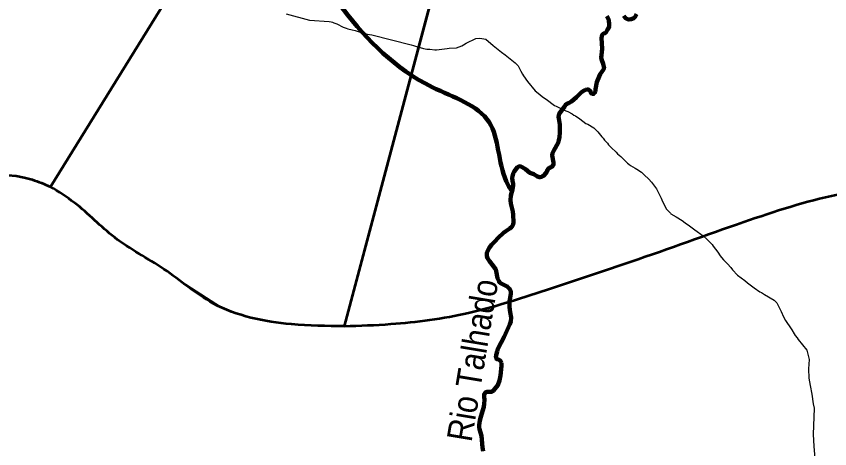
# Model space of a CAD drawing. Extents: x -1643653 to 4543381, y 1624270 to 13878484.
# Drawn here: x 611751 to 627893, y 8951494 to 8960077 of the extents above; entities that cross this region are included whole.
import ezdxf
from ezdxf.enums import TextEntityAlignment as Align

# ---------------------------------------------------------------- set-up
doc = ezdxf.new("R2010")
doc.units = 0
doc.header["$LTSCALE"] = 200
for name, color, linetype, lineweight in [('12', 7, 'Continuous', 25), ('23', 7, 'Continuous', 13), ('24', 7, 'Continuous', 25), ('28', 7, 'Continuous', 53), ('60', 7, 'Continuous', 13), ('9', 7, 'Continuous', 90)]:
    doc.layers.add(name, color=color, linetype=linetype, lineweight=lineweight)
doc.layers.add('49', color=7, linetype='Continuous')

msp = doc.modelspace()

# ---------------------------------------------------------------- linework, layer by layer
at = {"layer": '12'}
for points in [[(617107.9, 8960123.1), (617571.3, 8960000.1), (617961.2, 8959971.1), (617997, 8959967.1), (618026, 8959959.2), (618054, 8959949.2), (618114.7, 8959924.2), (618235.7, 8959862.3), (618293.7, 8959838.4), (618327.5, 8959827.4), (618413, 8959804.5), (618473.5, 8959791.6), (618533.2, 8959772.7), (618617.9, 8959748.8), (618652.5, 8959740.8), (618682.4, 8959731.8), (618711.4, 8959723.9), (618803.6, 8959709), (619586.3, 8959511.3)], [(619831.3, 8959436.2), (619865.1, 8959428.2), (619897.1, 8959423.3), (619929, 8959423.3), (619960.1, 8959421.4), (620056, 8959410.5), (620088, 8959410.6), (620193.3, 8959426.8), (620302, 8959438.9), (620338.3, 8959444), (620485.1, 8959452.2), (620592.3, 8959491.5), (620626.6, 8959508.6), (620677.1, 8959543.7), (620866.8, 8959636.1), (620950.1, 8959645.3), (621067.6, 8959622.4), (621213.8, 8959498.5), (621277.5, 8959446.5), (621310.7, 8959416.5), (621378.9, 8959364.5), (621451.2, 8959312.6), (621517.4, 8959257.6), (621620.6, 8959177.6), (621652, 8959151.6), (621681.1, 8959122.6), (621709.4, 8959090.6), (621730.8, 8959055.6), (621766, 8958989.6), (621797.6, 8958926.5), (621816.7, 8958894.5), (621897.9, 8958779.4), (622047.1, 8958598.4), (622104.4, 8958547.4), (622189, 8958482.4), (622295.2, 8958408.5), (622402.8, 8958323.5), (622432, 8958306.5), (622464.2, 8958290.6), (622503.3, 8958272.6), (622656.9, 8958198.7), (622695.9, 8958184.8), (622781.7, 8958137.8), (622814.5, 8958116.8), (622845, 8958100.9), (622933, 8958040.9), (622994, 8957997), (623055.6, 8957949), (623090.1, 8957935), (623208.6, 8957861.1), (623261.3, 8957811.1), (623293.1, 8957783.1), (623319, 8957753.1), (623370.1, 8957684.1), (623394.1, 8957657.1), (623423, 8957618), (623480.8, 8957556), (623503.5, 8957528), (623577.3, 8957455), (623634.3, 8957397), (623656.2, 8957377), (623681.5, 8957349), (623715.2, 8957318), (623746.4, 8957294), (623796.4, 8957250.1), (623820, 8957220), (623881.1, 8957162.1), (623907.7, 8957139.1), (623938.3, 8957116.1), (624032.6, 8957060.1), (624097.3, 8957025.2), (624126.4, 8957005.2), (624156.6, 8956982.2), (624209.6, 8956933.2), (624300.1, 8956843.2), (624356.6, 8956783.2), (624452.3, 8956653.2), (624547.5, 8956464), (624563.3, 8956437), (624643.8, 8956253.8), (624732.1, 8956169.8), (624741.4, 8956157.8), (624844.8, 8956096.9), (624963, 8956021), (625024.6, 8955976), (625106.9, 8955919.1), (625134.8, 8955896.1), (625215.8, 8955838.1), (625381.6, 8955722.2), (625453.3, 8955650.2), (625539.4, 8955570.2), (625559, 8955549.2), (625578.1, 8955517.2), (625672.3, 8955394.1), (625719.6, 8955321.1), (625744.1, 8955288.1), (625787.2, 8955246.1), (625865, 8955162.1), (625928.3, 8955090.1), (625962.8, 8955044), (626062.5, 8954941)], [(619586.3, 8959511.3), (619636.3, 8959496), (619674.1, 8959485), (619831.3, 8959436.2)], [(626062.5, 8954941), (626210.1, 8954830.1), (626263.6, 8954786.1), (626369.3, 8954710.2), (626395.7, 8954688.2), (626508.6, 8954610.2), (626539.2, 8954592.2), (626598.2, 8954554.3), (626792.1, 8954439.4), (626840.8, 8954390.4), (626864.8, 8954350.4), (626929.5, 8954214.3), (626976, 8954113.2), (627012.7, 8954042.1), (627056.3, 8953977.1), (627085.1, 8953931.1), (627140.4, 8953852), (627187.4, 8953773), (627209.8, 8953740), (627243.8, 8953694), (627268.1, 8953665), (627437.5, 8953449.9)], [(627437.5, 8953449.9), (627481.8, 8953267.7), (627474.2, 8953079.4), (627481, 8952894.1), (627502, 8952745.9), (627539.5, 8952577.7), (627565.1, 8952382.4), (627583.5, 8952301.3), (627578.9, 8952122), (627564.2, 8951783.5), (627578, 8951538.1), (627594.5, 8951309.8), (627615.6, 8951152.6), (627641.3, 8950944.3), (627690, 8950694), (627726.6, 8950540.8), (627780.8, 8950380.6), (627876.2, 8950172.5), (627886.3, 8950067.3), (627860.6, 8949911), (627825.7, 8949779.8), (627813.3, 8949686.6)]]:
    msp.add_lwpolyline(points, dxfattribs=at)
at = {"layer": '23'}
msp.add_lwpolyline([(612430.2, 8956693.8), (612747.6, 8956491.3), (613132.8, 8956184), (613551.6, 8955800.6), (614057.6, 8955452.3), (614550.7, 8955141.9), (615023.2, 8954818.1), (615915.6, 8954244.4), (616589.2, 8954040), (617511.2, 8953947.5), (618207.3, 8953925.8), (618257.6, 8953925.9)], dxfattribs=at)
msp.add_lwpolyline([(612430.2, 8956693.8), (612747.6, 8956491.3), (613132.8, 8956184), (613551.6, 8955800.6), (614057.6, 8955452.3), (614550.7, 8955141.9), (615023.2, 8954818.1), (615915.6, 8954244.4), (616589.2, 8954040), (617511.2, 8953947.5), (618207.3, 8953925.8), (618257.6, 8953925.9)], dxfattribs=at)
for points in [[(606946.8, 8954087), (607164, 8954388.6), (607396.1, 8954883.6), (607870.9, 8955517.4), (608625.2, 8956035.7), (609416.9, 8956401.3), (612068.3, 8956835.4), (612430.2, 8956693.8)], [(606946.8, 8954087), (607164, 8954388.6), (607396.1, 8954883.6), (607870.9, 8955517.4), (608625.2, 8956035.7), (609416.9, 8956401.3), (612068.3, 8956835.4), (612430.2, 8956693.8)], [(618257.6, 8953925.9), (619183.7, 8953970.3), (620725.9, 8954192.9), (622371.6, 8954682.1), (623953.8, 8955209.7), (626185.5, 8955995.2), (628043.5, 8956541.4), (631351.2, 8956802.4), (633709.5, 8956728.8), (635993.8, 8956280.5), (637686.3, 8955648.2), (639291.4, 8954828.8), (640588.9, 8953973.3), (641709, 8952948.6), (643376.9, 8951340.4), (644721.9, 8950215.5), (645793.1, 8949290.9)], [(618257.6, 8953925.9), (619183.7, 8953970.3), (620725.9, 8954192.9), (622371.6, 8954682.1), (623953.8, 8955209.7), (626185.5, 8955995.2), (628043.5, 8956541.4), (631351.2, 8956802.4), (633709.5, 8956728.8), (635993.8, 8956280.5), (637686.3, 8955648.2), (639291.4, 8954828.8), (640588.9, 8953973.3), (641709, 8952948.6), (643376.9, 8951340.4), (644721.9, 8950215.5), (645793.1, 8949290.9)]]:
    msp.add_spline(points, degree=3, dxfattribs=at)
at = {"layer": '24'}
for points in [[(624056.4, 8960117.9), (624029.7, 8960062.8), (624008.5, 8960040.7), (623952.6, 8960017.6), (623906.6, 8960011.5), (623879.7, 8960018.5), (623839.9, 8960041.5), (623809.1, 8960087.5)], [(623469.3, 8960080), (623503, 8960016.9), (623511.8, 8959991.9), (623518.8, 8959918.8), (623515.2, 8959871.7), (623503, 8959841.6), (623483.8, 8959814.6), (623458.3, 8959764.4), (623435.3, 8959743.4), (623405.8, 8959733.3), (623380.1, 8959708.2), (623370, 8959684.2), (623363, 8959639.1), (623374, 8959437.8), (623371.3, 8959365.7), (623362.7, 8959309.6), (623359.5, 8959254.5), (623367, 8959203.4), (623399.7, 8959131.4), (623414.8, 8959045.2), (623404.2, 8959022.2), (623338.3, 8958926.9), (623315, 8958880.8), (623272.9, 8958769.6), (623243.1, 8958633.3), (623241.6, 8958590.3), (623234, 8958561.2), (623207.1, 8958537.1), (623180.9, 8958538.1), (623154, 8958559.1), (623142.4, 8958588.1), (623129.2, 8958606.1), (623114.3, 8958616.1), (623091.3, 8958624.1), (623048.1, 8958618)], [(623048.1, 8958618), (623008.6, 8958598.9), (622961, 8958563.8), (622867, 8958474.5), (622765.3, 8958385.2), (622710.3, 8958350.1), (622672.6, 8958336), (622645.8, 8958310.9), (622635.8, 8958292.8), (622526.4, 8958139.4), (622516.5, 8958114.4), (622511.7, 8958078.3), (622515.3, 8958048.3), (622533.3, 8957971.2), (622537.7, 8957930.1), (622539.2, 8957771.9), (622532.6, 8957678.7), (622519.6, 8957617.6), (622503, 8957566.5), (622414.7, 8957413.1), (622392.8, 8957358), (622387.2, 8957313.9), (622413.1, 8957173.7), (622412, 8957144.7), (622401.3, 8957121.6), (622379.3, 8957091.6), (622329.5, 8957067.4), (622303.6, 8957046.4), (622292.3, 8957028.3), (622277.2, 8956988.2), (622224.7, 8956922.1), (622199.4, 8956902), (622173.6, 8956888.9), (622144.5, 8956882.9), (622124.1, 8956884.8), (622082.2, 8956903.8), (622023.4, 8956940.8)], [(622023.4, 8956940.8), (621940, 8956970.7), (621852.9, 8957044.7), (621852.9, 8957044.7), (621788.3, 8957084.6), (621747.1, 8957098.6), (621722, 8957094.5), (621699.9, 8957079.5), (621630.5, 8956993.2), (621609.1, 8956955.1), (621593, 8956869), (621597.7, 8956809.9), (621609.5, 8956752.8), (621610.3, 8956716.8), (621596.7, 8956635.6), (621564.2, 8956517.4), (621555.7, 8956425.2), (621563.4, 8956363.1), (621602.1, 8956205), (621612.3, 8956132.8), (621617.2, 8955989.6), (621609.4, 8955942.6), (621581.9, 8955900.4), (621546.5, 8955864.3), (621462.3, 8955810.1), (621421.6, 8955778), (621315.5, 8955681.7), (621248.5, 8955606.5), (621180.3, 8955539.2), (621144.2, 8955490.1), (621090.8, 8955387.9), (621089.6, 8955318.8), (621102.6, 8955276.7), (621141.2, 8955216.7), (621216.2, 8955123.7), (621263.9, 8955050.6), (621273.7, 8955018.6), (621298.4, 8954880.4), (621326.6, 8954818.3), (621344.8, 8954792.3), (621361.2, 8954778.3), (621494.9, 8954716.5), (621540.7, 8954668.5), (621556.5, 8954637.4), (621563.9, 8954607.4), (621564.5, 8954574.3), (621548.8, 8954491.2), (621540.9, 8954424.1), (621539.7, 8954301.9), (621548, 8954202.7), (621568.6, 8954096.6), (621562.7, 8954019.5), (621547, 8953964.4), (621433.8, 8953717.8), (621371.7, 8953602.5), (621309.6, 8953474.2), (621290.3, 8953424.1), (621271.3, 8953352), (621268.5, 8953307.9), (621278.3, 8953276.9), (621286.8, 8953268.9), (621318.5, 8953261.9), (621350.1, 8953247.9), (621369.2, 8953222.9), (621379.6, 8953197.9)], [(621379.6, 8953197.9), (621378.8, 8953137.8), (621359.7, 8952949.5), (621342.4, 8952846.3), (621307.8, 8952755.1), (621249.5, 8952681.9), (621219.1, 8952650.8), (621195, 8952631.7), (621171.1, 8952622.7), (621146.2, 8952620.6), (621100.1, 8952625.6), (621079.8, 8952621.5), (621057, 8952606.5), (621039.6, 8952581.4), (621035.3, 8952565.4), (621033.6, 8952527.3), (621045.1, 8952461.2), (621037.1, 8952383.1), (621025.7, 8952328), (620968.5, 8952127.6), (620952.3, 8952055.4), (620937.5, 8951961.3), (620936.1, 8951922.2), (620941.1, 8951883.2), (620980.3, 8951750), (621003, 8951516.7), (621017.4, 8951444.6)]]:
    msp.add_lwpolyline(points, dxfattribs=at)
at = {"layer": '28'}
msp.add_line((621434.1, 8965861.3), (618257.6, 8953925.9), dxfattribs=at)
for points in [[(620631.9, 8965673.6), (621434.1, 8965861.3), (618257.6, 8953925.9), (618257.6, 8953925.9)], [(612430.1, 8956693.8), (617911.2, 8965554.7), (618251.3, 8965287.2), (618322.3, 8965231.4)], [(612430.2, 8956693.8), (617911.2, 8965554.7), (618251.3, 8965287.2), (618322.3, 8965231.4)]]:
    msp.add_lwpolyline(points, dxfattribs=at)
for points in [[(606956.6, 8954077.8), (607164, 8954388.6), (607396.1, 8954883.6), (607870.9, 8955517.4), (608625.2, 8956035.7), (609416.9, 8956401.3), (612068.3, 8956835.4), (612430.2, 8956693.8)], [(618257.6, 8953925.9), (619183.7, 8953970.3), (620725.9, 8954192.9), (622371.6, 8954682.1), (623953.8, 8955209.7), (626185.5, 8955995.2), (628043.5, 8956541.4), (631351.2, 8956802.4), (633709.5, 8956728.8), (635993.8, 8956280.5), (637686.3, 8955648.2), (639291.4, 8954828.8), (640588.9, 8953973.3), (641709, 8952948.6), (643376.9, 8951340.4), (644721.9, 8950215.5), (645793.1, 8949290.9)], [(618257.6, 8953925.9), (617209.7, 8953965.7), (615658.4, 8954379), (614681.6, 8955057.1), (613704.6, 8955684.2), (612906.2, 8956374.2), (612430.2, 8956693.8)]]:
    msp.add_spline(points, degree=3, dxfattribs=at)
at = {"layer": '60', "lineweight": 25}
msp.add_spline([(814781, 9009175.5), (814787.2, 9009173.4), (814796.9, 9009173.4), (814799.4, 9009172.4), (814805.1, 9009174.5), (814805.6, 9009176.5), (814811.7, 9009179.5), (814811.7, 9009179.5), (814801.5, 9009181), (814790.7, 9009181.5), (814784.1, 9009183.1), (814777.4, 9009185.1), (814778.4, 9009175.5)], degree=3, dxfattribs=at)
at = {"layer": '9'}
for points in [[(624056.4, 8960117.9), (624029.7, 8960062.8), (624008.5, 8960040.7), (623952.6, 8960017.6), (623906.6, 8960011.5), (623879.7, 8960018.5), (623839.9, 8960041.5), (623809.1, 8960087.5)], [(623469.3, 8960080), (623503, 8960016.9), (623511.8, 8959991.9), (623518.8, 8959918.8), (623515.2, 8959871.7), (623503, 8959841.6), (623483.8, 8959814.6), (623458.3, 8959764.4), (623435.3, 8959743.4), (623405.8, 8959733.3), (623380.1, 8959708.2), (623370, 8959684.2), (623363, 8959639.1), (623374, 8959437.8), (623371.3, 8959365.7), (623362.7, 8959309.6), (623359.5, 8959254.5), (623367, 8959203.4), (623399.7, 8959131.4), (623414.8, 8959045.2), (623404.2, 8959022.2), (623338.3, 8958926.9), (623315, 8958880.8), (623272.9, 8958769.6), (623243.1, 8958633.3), (623241.6, 8958590.3), (623234, 8958561.2), (623207.1, 8958537.1), (623180.9, 8958538.1), (623154, 8958559.1), (623142.4, 8958588.1), (623129.2, 8958606.1), (623114.3, 8958616.1), (623091.3, 8958624.1), (623048.1, 8958618)], [(623048.1, 8958618), (623008.6, 8958598.9), (622961, 8958563.8), (622867, 8958474.5), (622765.3, 8958385.2), (622710.3, 8958350.1), (622672.6, 8958336), (622645.8, 8958310.9), (622635.8, 8958292.8), (622526.4, 8958139.4), (622516.5, 8958114.4), (622511.7, 8958078.3), (622515.3, 8958048.3), (622533.3, 8957971.2), (622537.7, 8957930.1), (622539.2, 8957771.9), (622532.6, 8957678.7), (622519.6, 8957617.6), (622503, 8957566.5), (622414.7, 8957413.1), (622392.8, 8957358), (622387.2, 8957313.9), (622413.1, 8957173.7), (622412, 8957144.7), (622401.3, 8957121.6), (622379.3, 8957091.6), (622329.5, 8957067.4), (622303.6, 8957046.4), (622292.3, 8957028.3), (622277.2, 8956988.2), (622224.7, 8956922.1), (622199.4, 8956902), (622173.6, 8956888.9), (622144.5, 8956882.9), (622124.1, 8956884.8), (622082.2, 8956903.8), (622023.4, 8956940.8)], [(622023.4, 8956940.8), (621940, 8956970.7), (621852.9, 8957044.7), (621852.9, 8957044.7), (621788.3, 8957084.6), (621747.1, 8957098.6), (621722, 8957094.5), (621699.9, 8957079.5), (621630.5, 8956993.2), (621609.1, 8956955.1), (621593, 8956869), (621597.7, 8956809.9), (621609.5, 8956752.8), (621610.3, 8956716.8), (621596.7, 8956635.6), (621564.2, 8956517.4), (621555.7, 8956425.2), (621563.4, 8956363.1), (621602.1, 8956205), (621612.3, 8956132.8), (621617.2, 8955989.6), (621609.4, 8955942.6), (621581.9, 8955900.4), (621546.5, 8955864.3), (621462.3, 8955810.1), (621421.6, 8955778), (621315.5, 8955681.7), (621248.5, 8955606.5), (621180.3, 8955539.2), (621144.2, 8955490.1), (621090.8, 8955387.9), (621089.6, 8955318.8), (621102.6, 8955276.7), (621141.2, 8955216.7), (621216.2, 8955123.7), (621263.9, 8955050.6), (621273.7, 8955018.6), (621298.4, 8954880.4), (621326.6, 8954818.3), (621344.8, 8954792.3), (621361.2, 8954778.3), (621494.9, 8954716.5), (621540.7, 8954668.5), (621556.5, 8954637.4), (621563.9, 8954607.4), (621564.5, 8954574.3), (621548.8, 8954491.2), (621540.9, 8954424.1), (621539.7, 8954301.9), (621548, 8954202.7), (621568.6, 8954096.6), (621562.7, 8954019.5), (621547, 8953964.4), (621433.8, 8953717.8), (621371.7, 8953602.5), (621309.6, 8953474.2), (621290.3, 8953424.1), (621271.3, 8953352), (621268.5, 8953307.9), (621278.3, 8953276.9), (621286.8, 8953268.9), (621318.5, 8953261.9), (621350.1, 8953247.9), (621369.2, 8953222.9), (621379.6, 8953197.9)], [(621379.6, 8953197.9), (621378.8, 8953137.8), (621359.7, 8952949.5), (621342.4, 8952846.3), (621307.8, 8952755.1), (621249.5, 8952681.9), (621219.1, 8952650.8), (621195, 8952631.7), (621171.1, 8952622.7), (621146.2, 8952620.6), (621100.1, 8952625.6), (621079.8, 8952621.5), (621057, 8952606.5), (621039.6, 8952581.4), (621035.3, 8952565.4), (621033.6, 8952527.3), (621045.1, 8952461.2), (621037.1, 8952383.1), (621025.7, 8952328), (620968.5, 8952127.6), (620952.3, 8952055.4), (620937.5, 8951961.3), (620936.1, 8951922.2), (620941.1, 8951883.2), (620980.3, 8951750), (621003, 8951516.7), (621017.4, 8951444.6)]]:
    msp.add_lwpolyline(points, dxfattribs=at)
msp.add_spline([(592698.5, 8977198.4), (599903.5, 8973292.7), (608459.2, 8968138.2), (612674.8, 8965332.6), (616842, 8962096.4), (620005, 8958671.2), (621134, 8957974.7), (621473.4, 8956805.3), (621586.2, 8956597.5)], degree=3, dxfattribs=at)

# ---------------------------------------------------------------- texts
at = {"layer": '49', "width": 0.9}
msp.add_text('Rio Talhado', height=500, rotation=80.538, dxfattribs=at).set_placement((621050.4, 8953212.3), align=Align.CENTER)

doc.saveas('drawing.dxf')
